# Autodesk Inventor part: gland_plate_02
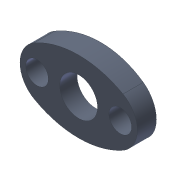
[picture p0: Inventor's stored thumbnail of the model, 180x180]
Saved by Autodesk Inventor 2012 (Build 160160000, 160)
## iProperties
Shininess: 64.0
Length Units: 11272
Angle Units: 11279
Time Units: 11290
Mass Units: 11286
Length Display Precision: 3
Angle Display Precision: 2
Company: Autodesk
Created: 2002-07
Part Number: gland_plate_02
Document SubType Name: Modeling
Designer: Lieven Grauls
Stock Number: gland_plate_02
Project: Valve Techcamp 2008
Density: 1 g/cm^3
Mass: 5.69967 g
Surface Area: 29.9208 cm^2
Volume: 5.69967 cm^3
Material: Default
Density: 0.0
Volumn: 0.0
Area: 0.0
PropertySet Name: Model Information
Control State: 0
Master: False
Checked Out: False
Author: Lieven Grauls
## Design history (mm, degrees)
sketch "Sketch1"
  geometry: L1 (-26.235, 15.081)-(31.644, 15.081); L2 (-28.399, -15.081)-(29.818, -15.081); L3 (-24.606, 28.626)-(-24.606, -27.535); L4 (24.606, 27.468)-(24.606, -26.03); A1 r 38.1 centre (0, -23.019) between (18.612, 10.226) and (-18.612, 10.226); A2 r 38.1 centre (0, 23.019) between (-18.612, -10.226) and (18.612, -10.226); A3 r 11.719 centre (-12.887, 0) between (-18.612, 10.226) and (-18.612, -10.226); A4 r 11.719 centre (12.887, 0) between (18.612, -10.226) and (18.612, 10.226); 1 further point
  constraints: 8 end point, 8 point on circle, 6 tangent, 4 centre point, 2 horizontal alignment, 2 parallel, 2 vertical alignment, 1 horizontal, 1 perpendicular
  dimensions: "d3" = 15.08125 distance from line of point (0, 0) L1 (= 0.5 x d5); "d5" = 30.1625 distance between parallel lines of L2 L1; "d10" = 49.2125 distance between parallel lines of L4 L3; "d12" = 24.60625 distance from line of point (0, 0) L3 (= 0.5 x d10); "d19" = 38.1 radius of A1; "d20" = 38.1 radius of A2 (derived); "d29" = 11.7094 dimension on A3 (derived)
extrude "Extrusion1" new body sketch "Sketch1" distance "d21" = 9.525; taper "d22" = 0 deg
sketch "Sketch2"
  geometry: L1 (-11.906, 24.942)-(-11.906, -13.155); L2 (0, -46.173)-(0, 184.952) reference; L3 (-18.612, 0)-(18.612, 0) reference; L4 (-24.606, 0)-(-24.606, 9.525) reference; L5 (24.606, 0)-(24.606, 9.525) reference; L6 (-24.606, 1.534)-(-24.606, -4.642); L7 (-24.606, -4.642)-(-11.906, -4.642); L8 (24.606, -4.642)-(24.606, 0); L9 (0, 0)-(0, -4.642); L10 (0, -4.642)-(0, 0); L11 (-11.906, 0)-(-11.906, -4.642); A1 r 152.4 centre (0, 151.934) between (-24.606, 1.534) and (-11.906, 0)
  constraints: 14 end point, 5 point on line, 2 collinear, 2 parallel, 2 point on circle, 1 centre point, 1 perpendicular, 1 vertical, 1 vertical alignment
  dimensions: "d25" = 23.8125 diameter of L1 L2; "d27" = 152.4 radius of A1
revolve "Revolution1" sketch "Sketch2" stored, may be unused: angle "d28" = 90 deg
sketch "Sketch3"
  geometry: L1 (-34.449, 0)-(34.449, 0) reference; 3 further points
  constraints: 2 point on line
  dimensions: "d30" = 17.4625 distance of point (-17.463, 0) point (0, 0); "d31" = 17.4625 distance of point (17.463, 0) point (0, 0) (= d30)
hole "Hole1" sketch "Sketch3" diameter "d32" = 9.525; stored, may be unused: countersink angle "d36" = 82 deg, drill point angle "d38" = 118 deg; dims "d33" = 12.7, "d34" = 9.525, "d35" = 6.35, "d37" = 19.05
sketch "Sketch4"
  geometry: L1 (-18.612, 9.525)-(18.612, 9.525) reference; L2 (-11.906, 0)-(11.906, 0) reference; L3 (-7.938, 9.525)-(-7.938, 2.291); L4 (-7.938, 2.291)-(-11.906, 0); L5 (0, -1.905)-(0, 11.43) reference; L6 (-7.938, 9.525)-(0, 9.525); L7 (-11.906, 0)-(0, 0); L8 (0, 9.525)-(0, 0)
  constraints: 10 end point, 2 collinear, 2 point on line, 1 midpoint, 1 perpendicular
  dimensions: "d46" = 15.875 diameter of L3 L5; "d47" = 30 deg angle of L2 L4
revolve "Revolution2" sketch "Sketch4" stored, may be unused: angle "d48" = 90 deg
sketch "Sketch5"
  geometry: L1 (-1, -1)-(-24.564, -1); L2 (-1, -1)-(-1, -15.068); L3 (0, 30.639)-(0, -22.701) reference; L4 (-34.449, 0)-(34.449, 0) reference; A1 r 11.719 centre (-12.887, 0) between (-18.612, 10.226) and (-18.612, -10.226) reference; A2 r 38.1 centre (0, 23.019) between (-18.612, -10.226) and (18.612, -10.226) reference; 1 further point
  constraints: 4 end point, 2 point on circle, 1 horizontal, 1 perpendicular
  dimensions: "d49" = 1 distance between parallel lines of L1 L4; "d50" = 1 distance between parallel lines of L3 L2 (= d49)
extrude "Extrusion2" cut sketch "Sketch5" stored distance "d51" = 25.4; taper "d52" = 0 deg
node "Volumenkörper1"
node "Volumenkörpern"
node "Oberflächenkörpern"
other parameters: "d23" = 152.4
